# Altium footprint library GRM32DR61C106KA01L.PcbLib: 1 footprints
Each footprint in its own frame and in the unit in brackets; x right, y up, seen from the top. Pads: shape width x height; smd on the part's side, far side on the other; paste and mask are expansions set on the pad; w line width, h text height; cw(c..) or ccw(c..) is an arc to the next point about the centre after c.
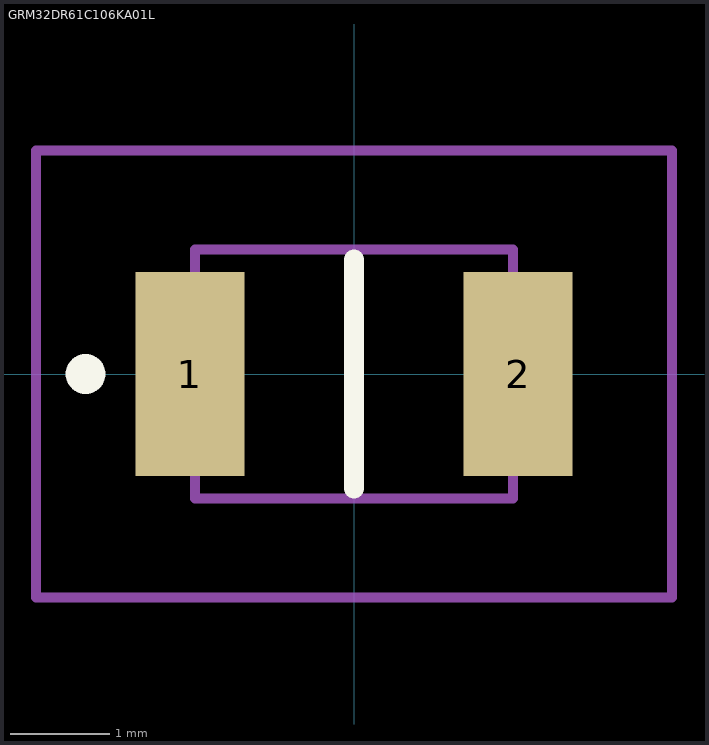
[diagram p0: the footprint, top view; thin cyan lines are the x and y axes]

## GRM32DR61C106KA01L [mm]
pads (2):
  rect 1.1x2.05 smd: 1(-1.65,0) 2(1.65,0)
Top Overlay:
  lines w0.2: 0,-1.15 0,1.15 ; -2.7,-0.1 cw(c-2.7,0) -2.7,0.1 ; -2.7,-0.1 -2.7,-0.1 ; -2.7,-0.1 ccw(c-2.7,0) -2.7,0.1 ; -2.7,0.1 -2.7,0.1
Mechanical 15:
  lines w0.1: -1.6,-1.25 1.6,-1.25 1.6,1.25 -1.6,1.25 -1.6,-1.25
Mechanical 20:
  lines w0.1: -3.2,-2.25 3.2,-2.25 3.2,2.25 -3.2,2.25 -3.2,-2.25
